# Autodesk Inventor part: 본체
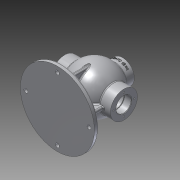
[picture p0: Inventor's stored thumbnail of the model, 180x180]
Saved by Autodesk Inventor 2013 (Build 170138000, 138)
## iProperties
Created: 2020-08
Part Number: 본체
Material: 알루미늄 6061
Document SubType Name: Modeling
Designer: 99
Density: 1 g/cm^3
Author: 99
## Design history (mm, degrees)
sketch "스케치1"
  geometry: L1 (-42.988, 31)-(-68, 31); L2 (42.988, 31)-(68, 31); L3 (-68, 0)-(68, 0); L4 (0, 53)-(0, -53); L5 (-68, 31)-(-68, 17.5); L6 (68, 31)-(68, 17.5); L7 (-68, 17.5)-(-52, 17.5); L8 (-52, 17.5)-(-39.278, 17.5); L9 (52, 18.5)-(50.25, 18.5); L10 (52, 17.5)-(52, 18.5); L11 (50.25, 18.5)-(50.25, 17.5); L12 (39.278, 17.5)-(50.25, 17.5); L13 (52, 17.5)-(68, 17.5); A1 r 43 centre (0, 0) between (39.278, 17.5) and (-39.278, 17.5); A2 r 53 centre (0, 0) between (42.988, 31) and (-42.988, 31); 5 further points
  constraints: 26 end point, 5 collinear, 5 perpendicular, 4 coincident, 4 point on circle, 3 midpoint, 2 centre point, 2 horizontal, 1 horizontal alignment, 1 symmetric about line, 1 other
  dimensions: "d9" = 43 radius of A1; "d12" = 136 distance between parallel lines of L6 L5; "d19" = 53 radius of A2; "d20" = 62 diameter of L1 L3; "d21" = 35 diameter of L7 L3; "d88" = 1.75 distance of L9.start L9.end; "d89" = 37 diameter of L9 L3; "d90" = 16 distance between parallel lines of L6 L10
revolve "회전1" sketch "스케치1" stored, may be unused: angle "d23" = 90 deg
node "작업 평면1"
sketch "스케치2"
  geometry: C1 r 27 at (0, 0); 1 further point
  constraints: 1 centre point, 1 coincident
  dimensions: "d25" = 54 diameter of C1
extrude "돌출1" join sketch "스케치2" stored distance "d26" = 10; taper "d27" = 0 deg
sketch "스케치3"
  geometry: C1 r 27 at (0, 0) reference
hole "구멍1" diameter "d30" = 26; stored, may be unused: countersink angle "d34" = 90 deg, drill point angle "d36" = 118 deg; dims "d28" = 10, "d29" = 10, "d31" = 6, "d32" = 4, "d33" = 2, "d35" = 8
sketch "스케치4" dims "d37" = 40
  geometry: C1 r 13 at (0, 0) reference; C2 r 27 at (0, 0) reference; 2 further points
  constraints: 2 vertical alignment, 1 coincident, 2 other
hole "구멍2" sketch "스케치4" at (0, 20) diameter "d38" = 3.242; stored, may be unused: countersink angle "d42" = 82 deg, drill point angle "d44" = 118 deg; dims "d39" = 12, "d40" = 3.023, "d41" = 2, "d43" = 15
sketch "스케치5" dims "d48" = 48
  geometry: C1 r 17.5 at (0, 0) reference; C2 r 31 at (0, 0) reference; 2 further points
  constraints: 3 coincident, 2 vertical alignment, 2 other
hole "구멍3" sketch "스케치5" at (0, 24) diameter "d49" = 3.242; stored, may be unused: countersink angle "d53" = 82 deg, drill point angle "d55" = 118 deg; dims "d50" = 12, "d51" = 3.023, "d52" = 2, "d54" = 15
node "작업 평면2"
sketch "스케치6" dims "d60" = 170
  geometry: L1 (-4, 52)-(4, 52); L2 (4, -52)-(-4, -52); L3 (52, 4)-(52, -4); L4 (-52, -4)-(-52, 4); L5 (-52, 4)-(-4, 4); L6 (4, 4)-(52, 4); L7 (52, -4)-(4, -4); L8 (-4, -4)-(-52, -4); L9 (-4, -52)-(-4, -4); L10 (-4, 4)-(-4, 52); L11 (4, 52)-(4, 4); L12 (4, -4)-(4, -52); L13 (0, 52)-(0, -52); L14 (-85, 0)-(-72.5, 0); 5 further points
  constraints: 28 end point, 10 parallel, 5 midpoint, 5 perpendicular, 4 collinear, 3 horizontal, 3 horizontal alignment, 1 coincident, 1 vertical alignment, 4 other
  dimensions: "d62" = 8 distance between parallel lines of L10 L11; "d63" = 8 distance of L3.start L3.end; "d64" = 104 distance from line of L1.end L2; "d65" = 104 distance from line of L3 point (-52, 0)
extrude "돌출2" join sketch "스케치6" distance "d66" = 10; taper "d67" = 0 deg
extrude "돌출3" join sketch "스케치6" stored distance "d68" = 10; taper "d69" = 0 deg
node "작업 평면3"
sketch "스케치7"
  geometry: L1 (27, 65)-(27, 45.607) reference; L2 (-27, 45.607)-(27, 45.607) reference; L3 (-27, 65)-(27, 65) reference; L4 (-27, 65)-(-27, 45.607) reference; L5 (-27, 65)-(-27, 45.607) reference; 2 further points
  constraints: 1 other
  dimensions: "d86" = 27 distance from line of point (0, 56) L4; "d87" = 9 distance from line of point (0, 56) L3
feature "엠보싱1" sketch "스케치7" dims "d71" = 0.5, "d72" = 0
fillet "모깎기1" dims "d73" = 3
sketch "스케치8" dims "d74" = 145
  geometry: C1 r 82 at (0, 0) reference; 2 further points
  constraints: 2 vertical alignment, 1 coincident, 2 other
hole "구멍4" sketch "스케치8" at (0, 72.5) diameter "d76" = 9; stored, may be unused: countersink angle "d80" = 90 deg, drill point angle "d82" = 118 deg; dims "d77" = 6, "d78" = 4, "d79" = 2, "d81" = 8
chamfer "모따기1" distance "d91" = 1; stored, may be unused: second distance "d92" = 2, angle "d93" = 45 deg
node "솔리드1"
pattern_circular "원형 패턴1" dims angle "d46" = 360 deg
pattern_circular "원형 패턴2" dims angle "d57" = 360 deg
mirror "대칭1"
pattern_circular "원형 패턴3" dims angle "d84" = 360 deg
node "투영된 루프1"
other parameters: "d0" = 106, "d1" = 136, "d7" = 136, "d8" = 86, "d16" = 106, "d18" = 53, "d24" = 65, "d70" = 89.5
